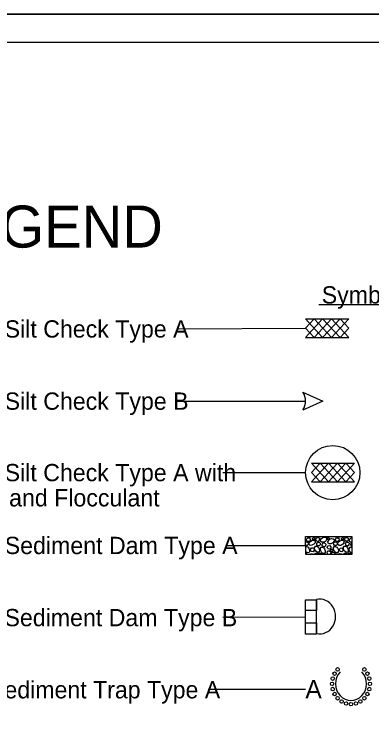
# Model space of a CAD drawing. Extents: x 1677124 to 1678808, y 1331209 to 1332299.
# Drawn here: x 1678246 to 1678527, y 1331745 to 1332299 of the extents above; entities that cross this region are included whole.
import ezdxf

# ---------------------------------------------------------------- set-up
doc = ezdxf.new("R2010")
doc.units = 0
for name, color, linetype in [('EC Title Sheet CELL', 7, 'Continuous'), ('Old_Level_1', 7, 'Continuous'), ('Sheet Plan CELL', 7, 'Continuous'), ('Sheet Plot Border Outside CELL', 7, 'Continuous'), ('z - Construction', 7, 'Continuous')]:
    doc.layers.add(name, color=color, linetype=linetype)

msp = doc.modelspace()

# ---------------------------------------------------------------- linework, layer by layer
at = {"layer": 'EC Title Sheet CELL'}
for p, q in [((1678485.11, 1332070.62), (1678547.36, 1332070.65)), ((1678481.61, 1332059.43), (1678474.81, 1332052.07)), ((1678474.83, 1332059.43), (1678508.58, 1332059.45)), ((1678488.15, 1332044.75), (1678474.83, 1332059.43)), ((1678488.17, 1332059.45), (1678474.85, 1332044.75)), ((1678495.22, 1332044.77), (1678481.61, 1332059.43)), ((1678495.22, 1332059.43), (1678481.63, 1332044.75)), ((1678501.78, 1332059.45), (1678488.15, 1332044.75)), ((1678501.78, 1332044.75), (1678488.17, 1332059.45)), ((1678508.58, 1332059.45), (1678495.22, 1332044.77)), ((1678508.58, 1332044.75), (1678495.22, 1332059.43)), ((1678508.58, 1332052.09), (1678501.78, 1332059.45)), ((1678375.11, 1332051.54), (1678474.81, 1332052.07)), ((1678481.63, 1332044.75), (1678474.81, 1332052.07)), ((1678508.58, 1332052.09), (1678501.78, 1332044.75)), ((1678474.85, 1332044.75), (1678508.58, 1332044.75)), ((1678472.7, 1332001.89), (1678488.4, 1331994.82)), ((1678374.14, 1331994.92), (1678474.81, 1331995)), ((1678488.4, 1331994.82), (1678472.7, 1331987.78)), ((1678486.23, 1331946.17), (1678479.43, 1331938.82)), ((1678492.77, 1331931.5), (1678479.45, 1331946.17)), ((1678479.45, 1331946.17), (1678513.18, 1331946.17)), ((1678492.79, 1331946.19), (1678479.47, 1331931.5)), ((1678499.84, 1331931.52), (1678486.23, 1331946.17)), ((1678499.84, 1331946.17), (1678486.25, 1331931.5)), ((1678506.4, 1331946.19), (1678492.77, 1331931.5)), ((1678506.4, 1331931.5), (1678492.79, 1331946.19)), ((1678513.2, 1331946.19), (1678499.84, 1331931.52)), ((1678513.2, 1331931.5), (1678499.84, 1331946.17)), ((1678513.2, 1331938.84), (1678506.4, 1331946.19)), ((1678410.01, 1331938.84), (1678474.81, 1331938.84)), ((1678486.25, 1331931.5), (1678479.43, 1331938.82)), ((1678513.2, 1331938.84), (1678506.4, 1331931.5)), ((1678479.47, 1331931.5), (1678513.2, 1331931.5)), ((1678412.2, 1331881.69), (1678474.81, 1331881.76)), ((1678474.67, 1331812.19), (1678474.69, 1331839.01)), ((1678474.67, 1331812.19), (1678474.69, 1331839.01)), ((1678483.31, 1331812.19), (1678483.32, 1331839.01)), ((1678483.31, 1331812.19), (1678483.32, 1331839.01)), ((1678409.88, 1331825.52), (1678474.68, 1331825.6)), ((1678483.31, 1331812.19), (1678474.67, 1331812.19)), ((1678483.31, 1331812.19), (1678474.67, 1331812.19)), ((1678398.44, 1331768.88), (1678474.68, 1331768.98))]:
    msp.add_line(p, q, dxfattribs=at)
for points in [[(1678474.69, 1331888.83), (1678511.07, 1331888.83), (1678511.09, 1331874.69), (1678474.93, 1331874.69)], [(1678474.69, 1331888.83), (1678511.07, 1331888.83), (1678511.09, 1331874.69), (1678474.93, 1331874.69)], [(1678474.69, 1331839.01), (1678483.32, 1331839.01), (1678483.31, 1331830.53), (1678474.69, 1331830.55)], [(1678474.67, 1331820.95), (1678483.32, 1331820.95), (1678483.31, 1331812.19), (1678474.67, 1331812.19)]]:
    msp.add_lwpolyline(points, close=True, dxfattribs=at)
for points in [[(1678474.95, 1331884.59), (1678474.95, 1331884.59), (1678475.99, 1331884.59), (1678477.05, 1331883.76), (1678476.77, 1331882.31), (1678475.99, 1331881.76), (1678474.95, 1331881.76), (1678474.95, 1331881.76)], [(1678474.95, 1331884.59), (1678474.95, 1331884.59), (1678475.99, 1331884.59), (1678477.05, 1331883.76), (1678476.77, 1331882.31), (1678475.99, 1331881.76), (1678474.95, 1331881.76), (1678474.95, 1331881.76)], [(1678475.46, 1331886.57), (1678476.5, 1331887.69), (1678477.54, 1331887.69), (1678478.37, 1331886.84), (1678478.34, 1331885.43), (1678477.56, 1331884.88), (1678476.24, 1331884.88), (1678475.75, 1331885.43), (1678475.46, 1331886.57)], [(1678475.46, 1331886.57), (1678476.5, 1331887.69), (1678477.54, 1331887.69), (1678478.37, 1331886.84), (1678478.34, 1331885.43), (1678477.56, 1331884.88), (1678476.24, 1331884.88), (1678475.75, 1331885.43), (1678475.46, 1331886.57)], [(1678479.13, 1331888.81), (1678478.87, 1331888.24), (1678477.56, 1331888.26), (1678477.31, 1331888.81)], [(1678479.13, 1331888.81), (1678478.87, 1331888.24), (1678477.56, 1331888.26), (1678477.31, 1331888.81)], [(1678478.87, 1331885.16), (1678480.17, 1331885.73), (1678481.49, 1331885.71), (1678482.27, 1331884.86), (1678482.27, 1331883.74), (1678481.21, 1331882.6), (1678479.66, 1331881.78), (1678478.34, 1331881.76), (1678477.54, 1331882.31), (1678477.56, 1331883.47), (1678478.07, 1331884.57), (1678478.87, 1331885.16)], [(1678478.87, 1331885.16), (1678480.17, 1331885.73), (1678481.49, 1331885.71), (1678482.27, 1331884.86), (1678482.27, 1331883.74), (1678481.21, 1331882.6), (1678479.66, 1331881.78), (1678478.34, 1331881.76), (1678477.54, 1331882.31), (1678477.56, 1331883.47), (1678478.07, 1331884.57), (1678478.87, 1331885.16)], [(1678480.17, 1331887.14), (1678480.7, 1331887.69), (1678481.47, 1331887.69), (1678482.02, 1331887.12), (1678482, 1331886.27), (1678481.24, 1331885.98), (1678480.68, 1331886), (1678480.17, 1331886.28), (1678480.17, 1331887.14)], [(1678480.17, 1331887.14), (1678480.7, 1331887.69), (1678481.47, 1331887.69), (1678482.02, 1331887.12), (1678482, 1331886.27), (1678481.24, 1331885.98), (1678480.68, 1331886), (1678480.17, 1331886.28), (1678480.17, 1331887.14)], [(1678483.06, 1331888.83), (1678482.8, 1331888.24), (1678481.49, 1331888.26), (1678481.23, 1331888.81)], [(1678483.06, 1331888.83), (1678482.8, 1331888.24), (1678481.49, 1331888.26), (1678481.23, 1331888.81)], [(1678482.78, 1331886.55), (1678483.59, 1331887.69), (1678484.88, 1331887.98), (1678485.69, 1331887.12), (1678485.4, 1331885.71), (1678484.63, 1331884.86), (1678483.57, 1331885.16), (1678482.8, 1331885.71), (1678482.78, 1331886.55)], [(1678482.78, 1331886.55), (1678483.59, 1331887.69), (1678484.88, 1331887.98), (1678485.69, 1331887.12), (1678485.4, 1331885.71), (1678484.63, 1331884.86), (1678483.57, 1331885.16), (1678482.8, 1331885.71), (1678482.78, 1331886.55)], [(1678483.61, 1331883.17), (1678484.36, 1331884.29), (1678485.4, 1331884.29), (1678486.2, 1331883.47), (1678486.2, 1331882.05), (1678485.42, 1331881.5), (1678484.36, 1331881.48), (1678483.57, 1331882.03), (1678483.61, 1331883.17)], [(1678483.61, 1331883.17), (1678484.36, 1331884.29), (1678485.4, 1331884.29), (1678486.2, 1331883.47), (1678486.2, 1331882.05), (1678485.42, 1331881.5), (1678484.36, 1331881.48), (1678483.57, 1331882.03), (1678483.61, 1331883.17)], [(1678488.05, 1331887.69), (1678489.34, 1331888.26), (1678490.64, 1331888.24), (1678491.17, 1331887.41), (1678491.17, 1331886.28), (1678490.38, 1331884.88), (1678488.82, 1331884.31), (1678487.52, 1331884.31), (1678486.73, 1331884.88), (1678486.46, 1331886), (1678487.24, 1331887.12), (1678488.05, 1331887.69)], [(1678488.05, 1331887.69), (1678489.34, 1331888.26), (1678490.64, 1331888.24), (1678491.17, 1331887.41), (1678491.17, 1331886.28), (1678490.38, 1331884.88), (1678488.82, 1331884.31), (1678487.52, 1331884.31), (1678486.73, 1331884.88), (1678486.46, 1331886), (1678487.24, 1331887.12), (1678488.05, 1331887.69)], [(1678490.13, 1331888.81), (1678490.13, 1331888.55), (1678488.81, 1331888.55), (1678488.81, 1331888.81)], [(1678490.13, 1331888.81), (1678490.13, 1331888.55), (1678488.81, 1331888.55), (1678488.81, 1331888.81)], [(1678491.68, 1331887.12), (1678492.23, 1331887.96), (1678492.75, 1331887.98), (1678493.27, 1331887.39), (1678493.28, 1331886.55), (1678492.74, 1331886.27), (1678491.94, 1331886.28), (1678491.7, 1331886.57), (1678491.68, 1331887.12)], [(1678491.68, 1331887.12), (1678492.23, 1331887.96), (1678492.75, 1331887.98), (1678493.27, 1331887.39), (1678493.28, 1331886.55), (1678492.74, 1331886.27), (1678491.94, 1331886.28), (1678491.7, 1331886.57), (1678491.68, 1331887.12)], [(1678493.51, 1331886.55), (1678495.1, 1331887.14), (1678496.4, 1331886.84), (1678497.2, 1331886.28), (1678497.2, 1331885.16), (1678496.14, 1331883.74), (1678494.59, 1331882.9), (1678493.25, 1331882.88), (1678492.47, 1331883.45), (1678492.23, 1331884.59), (1678493, 1331885.71), (1678493.78, 1331886.55)], [(1678493.51, 1331886.55), (1678495.1, 1331887.14), (1678496.4, 1331886.84), (1678497.2, 1331886.28), (1678497.2, 1331885.16), (1678496.14, 1331883.74), (1678494.59, 1331882.9), (1678493.25, 1331882.88), (1678492.47, 1331883.45), (1678492.23, 1331884.59), (1678493, 1331885.71), (1678493.78, 1331886.55)], [(1678496.65, 1331883.45), (1678497.73, 1331884.57), (1678498.77, 1331884.59), (1678499.54, 1331883.74), (1678499.54, 1331882.33), (1678498.75, 1331881.76), (1678497.48, 1331881.76), (1678496.93, 1331882.33), (1678496.65, 1331883.45)], [(1678496.65, 1331883.45), (1678497.73, 1331884.57), (1678498.77, 1331884.59), (1678499.54, 1331883.74), (1678499.54, 1331882.33), (1678498.75, 1331881.76), (1678497.48, 1331881.76), (1678496.93, 1331882.33), (1678496.65, 1331883.45)], [(1678498.24, 1331886.55), (1678499.01, 1331887.69), (1678500.05, 1331887.69), (1678501.13, 1331886.85), (1678500.85, 1331885.43), (1678500.09, 1331884.86), (1678499.03, 1331884.86), (1678498.48, 1331885.43), (1678498.24, 1331886.55)], [(1678498.24, 1331886.55), (1678499.01, 1331887.69), (1678500.05, 1331887.69), (1678501.13, 1331886.85), (1678500.85, 1331885.43), (1678500.09, 1331884.86), (1678499.03, 1331884.86), (1678498.48, 1331885.43), (1678498.24, 1331886.55)], [(1678501.9, 1331888.81), (1678501.37, 1331888.24), (1678500.07, 1331888.26), (1678499.81, 1331888.81)], [(1678501.9, 1331888.81), (1678501.37, 1331888.24), (1678500.07, 1331888.26), (1678499.81, 1331888.81)], [(1678501.39, 1331885.14), (1678502.98, 1331885.71), (1678504.26, 1331885.73), (1678504.78, 1331884.88), (1678504.78, 1331883.76), (1678503.98, 1331882.62), (1678502.41, 1331881.76), (1678501.13, 1331881.76), (1678500.07, 1331882.33), (1678500.07, 1331883.47), (1678500.6, 1331884.59), (1678501.39, 1331885.14)], [(1678501.39, 1331885.14), (1678502.98, 1331885.71), (1678504.26, 1331885.73), (1678504.78, 1331884.88), (1678504.78, 1331883.76), (1678503.98, 1331882.62), (1678502.41, 1331881.76), (1678501.13, 1331881.76), (1678500.07, 1331882.33), (1678500.07, 1331883.47), (1678500.6, 1331884.59), (1678501.39, 1331885.14)], [(1678502.96, 1331887.12), (1678503.21, 1331887.69), (1678504.02, 1331887.67), (1678504.53, 1331887.12), (1678504.51, 1331886.27), (1678504, 1331886), (1678503.22, 1331886), (1678502.96, 1331886.28), (1678502.96, 1331887.12)], [(1678502.96, 1331887.12), (1678503.21, 1331887.69), (1678504.02, 1331887.67), (1678504.53, 1331887.12), (1678504.51, 1331886.27), (1678504, 1331886), (1678503.22, 1331886), (1678502.96, 1331886.28), (1678502.96, 1331887.12)], [(1678505.82, 1331888.81), (1678505.57, 1331888.26), (1678504.26, 1331888.26), (1678504, 1331888.83)], [(1678505.82, 1331888.81), (1678505.57, 1331888.26), (1678504.26, 1331888.26), (1678504, 1331888.83)], [(1678505.29, 1331886.55), (1678506.08, 1331887.69), (1678507.4, 1331887.96), (1678508.18, 1331887.12), (1678508.18, 1331885.71), (1678507.4, 1331885.14), (1678506.12, 1331885.14), (1678505.57, 1331885.71), (1678505.29, 1331886.55)], [(1678505.29, 1331886.55), (1678506.08, 1331887.69), (1678507.4, 1331887.96), (1678508.18, 1331887.12), (1678508.18, 1331885.71), (1678507.4, 1331885.14), (1678506.12, 1331885.14), (1678505.57, 1331885.71), (1678505.29, 1331886.55)], [(1678506.1, 1331883.19), (1678506.87, 1331884.31), (1678508.18, 1331884.31), (1678508.97, 1331883.45), (1678508.71, 1331882.07), (1678508.18, 1331881.48), (1678506.86, 1331881.48), (1678506.34, 1331882.05), (1678506.1, 1331883.19)], [(1678506.1, 1331883.19), (1678506.87, 1331884.31), (1678508.18, 1331884.31), (1678508.97, 1331883.45), (1678508.71, 1331882.07), (1678508.18, 1331881.48), (1678506.86, 1331881.48), (1678506.34, 1331882.05), (1678506.1, 1331883.19)], [(1678511.05, 1331884.31), (1678510.01, 1331884.31), (1678509.24, 1331884.88), (1678509.22, 1331886), (1678509.75, 1331887.14), (1678510.52, 1331887.69)], [(1678511.05, 1331884.31), (1678510.01, 1331884.31), (1678509.24, 1331884.88), (1678509.22, 1331886), (1678509.75, 1331887.14), (1678510.52, 1331887.69)], [(1678510.52, 1331887.69), (1678511.07, 1331887.71)], [(1678510.52, 1331887.69), (1678511.07, 1331887.71)], [(1678474.69, 1331880.92), (1678475.73, 1331880.92), (1678476.77, 1331880.37), (1678477.3, 1331879.52)], [(1678474.69, 1331880.92), (1678475.73, 1331880.92), (1678476.77, 1331880.37), (1678477.3, 1331879.52)], [(1678477.3, 1331879.52), (1678477.81, 1331878.07), (1678477.83, 1331876.69), (1678477.3, 1331876.14), (1678475.99, 1331875.83), (1678474.69, 1331876.99)], [(1678477.3, 1331879.52), (1678477.81, 1331878.07), (1678477.83, 1331876.69), (1678477.3, 1331876.14), (1678475.99, 1331875.83), (1678474.69, 1331876.99)], [(1678478.6, 1331878.38), (1678479.38, 1331879.78), (1678480.7, 1331879.78), (1678481.47, 1331878.64), (1678481.24, 1331877.52), (1678480.72, 1331876.71), (1678479.38, 1331876.95), (1678478.87, 1331877.54), (1678478.6, 1331878.38)], [(1678478.6, 1331878.38), (1678479.38, 1331879.78), (1678480.7, 1331879.78), (1678481.47, 1331878.64), (1678481.24, 1331877.52), (1678480.72, 1331876.71), (1678479.38, 1331876.95), (1678478.87, 1331877.54), (1678478.6, 1331878.38)], [(1678485.16, 1331879.78), (1678485.67, 1331878.11), (1678485.4, 1331876.97), (1678484.89, 1331876.12), (1678483.85, 1331876.4), (1678482.8, 1331877.26), (1678481.74, 1331878.64), (1678482.02, 1331880.35), (1678482.53, 1331881.21), (1678483.57, 1331881.21), (1678484.36, 1331880.64), (1678485.16, 1331879.78)], [(1678485.16, 1331879.78), (1678485.67, 1331878.11), (1678485.4, 1331876.97), (1678484.89, 1331876.12), (1678483.85, 1331876.4), (1678482.8, 1331877.26), (1678481.74, 1331878.64), (1678482.02, 1331880.35), (1678482.53, 1331881.21), (1678483.57, 1331881.21), (1678484.36, 1331880.64), (1678485.16, 1331879.78)], [(1678489.6, 1331878.95), (1678490.11, 1331877.54), (1678490.13, 1331876.12), (1678489.6, 1331875.26), (1678488.31, 1331875.28), (1678487.24, 1331876.4), (1678486.44, 1331878.09), (1678486.46, 1331879.52), (1678486.97, 1331880.35), (1678488.01, 1331880.35), (1678489.07, 1331879.78), (1678489.6, 1331878.95)], [(1678489.6, 1331878.95), (1678490.11, 1331877.54), (1678490.13, 1331876.12), (1678489.6, 1331875.26), (1678488.31, 1331875.28), (1678487.24, 1331876.4), (1678486.44, 1331878.09), (1678486.46, 1331879.52), (1678486.97, 1331880.35), (1678488.01, 1331880.35), (1678489.07, 1331879.78), (1678489.6, 1331878.95)], [(1678487.77, 1331882.31), (1678488.3, 1331883.76), (1678489.62, 1331883.74), (1678490.66, 1331882.62), (1678490.39, 1331881.5), (1678489.6, 1331880.62), (1678488.54, 1331880.92), (1678487.78, 1331881.48), (1678487.77, 1331882.31)], [(1678487.77, 1331882.31), (1678488.3, 1331883.76), (1678489.62, 1331883.74), (1678490.66, 1331882.62), (1678490.39, 1331881.5), (1678489.6, 1331880.62), (1678488.54, 1331880.92), (1678487.78, 1331881.48), (1678487.77, 1331882.31)], [(1678491.68, 1331880.35), (1678492.47, 1331881.5), (1678493.79, 1331881.76), (1678494.57, 1331880.64), (1678494.57, 1331879.52), (1678493.78, 1331878.64), (1678492.47, 1331878.93), (1678491.96, 1331879.5), (1678491.68, 1331880.35)], [(1678491.68, 1331880.35), (1678492.47, 1331881.5), (1678493.79, 1331881.76), (1678494.57, 1331880.64), (1678494.57, 1331879.52), (1678493.78, 1331878.64), (1678492.47, 1331878.93), (1678491.96, 1331879.5), (1678491.68, 1331880.35)], [(1678494.32, 1331878.09), (1678494.85, 1331878.66), (1678495.63, 1331878.66), (1678496.14, 1331878.38), (1678496.14, 1331877.52), (1678495.61, 1331876.95), (1678494.83, 1331876.95), (1678494.59, 1331877.52), (1678494.32, 1331878.09)], [(1678494.32, 1331878.09), (1678494.85, 1331878.66), (1678495.63, 1331878.66), (1678496.14, 1331878.38), (1678496.14, 1331877.52), (1678495.61, 1331876.95), (1678494.83, 1331876.95), (1678494.59, 1331877.52), (1678494.32, 1331878.09)], [(1678500.07, 1331879.5), (1678500.58, 1331878.09), (1678500.33, 1331876.69), (1678499.81, 1331875.85), (1678498.77, 1331875.83), (1678497.46, 1331876.95), (1678496.67, 1331878.66), (1678496.67, 1331880.07), (1678497.2, 1331880.92), (1678498.24, 1331880.92), (1678499.29, 1331880.35), (1678499.81, 1331879.5)], [(1678500.07, 1331879.5), (1678500.58, 1331878.09), (1678500.33, 1331876.69), (1678499.81, 1331875.85), (1678498.77, 1331875.83), (1678497.46, 1331876.95), (1678496.67, 1331878.66), (1678496.67, 1331880.07), (1678497.2, 1331880.92), (1678498.24, 1331880.92), (1678499.29, 1331880.35), (1678499.81, 1331879.5)], [(1678501.37, 1331878.38), (1678501.89, 1331879.5), (1678503.22, 1331879.78), (1678504, 1331878.66), (1678504, 1331877.54), (1678503.21, 1331876.67), (1678502.18, 1331876.95), (1678501.39, 1331877.52), (1678501.37, 1331878.38)], [(1678501.37, 1331878.38), (1678501.89, 1331879.5), (1678503.22, 1331879.78), (1678504, 1331878.66), (1678504, 1331877.54), (1678503.21, 1331876.67), (1678502.18, 1331876.95), (1678501.39, 1331877.52), (1678501.37, 1331878.38)], [(1678507.65, 1331879.78), (1678508.18, 1331878.4), (1678508.18, 1331876.95), (1678507.67, 1331876.12), (1678506.61, 1331876.42), (1678505.3, 1331877.24), (1678504.51, 1331878.66), (1678504.51, 1331880.35), (1678505.04, 1331881.19), (1678506.08, 1331881.19), (1678507.14, 1331880.62), (1678507.65, 1331879.78)], [(1678507.65, 1331879.78), (1678508.18, 1331878.4), (1678508.18, 1331876.95), (1678507.67, 1331876.12), (1678506.61, 1331876.42), (1678505.3, 1331877.24), (1678504.51, 1331878.66), (1678504.51, 1331880.35), (1678505.04, 1331881.19), (1678506.08, 1331881.19), (1678507.14, 1331880.62), (1678507.65, 1331879.78)], [(1678511.07, 1331875.26), (1678511.07, 1331875.26), (1678509.75, 1331876.38), (1678508.99, 1331878.09), (1678509.22, 1331879.5), (1678509.75, 1331880.35), (1678510.8, 1331880.35), (1678511.07, 1331880.09)], [(1678511.07, 1331875.26), (1678511.07, 1331875.26), (1678509.75, 1331876.38), (1678508.99, 1331878.09), (1678509.22, 1331879.5), (1678509.75, 1331880.35), (1678510.8, 1331880.35), (1678511.07, 1331880.09)], [(1678510.28, 1331882.62), (1678511.05, 1331883.74)], [(1678510.28, 1331882.62), (1678511.05, 1331883.74)], [(1678511.09, 1331880.91), (1678511.09, 1331880.91), (1678510.52, 1331881.48), (1678510.28, 1331882.62)], [(1678511.09, 1331880.91), (1678511.09, 1331880.91), (1678510.52, 1331881.48), (1678510.28, 1331882.62)], [(1678474.95, 1331875.83), (1678475.22, 1331875.55), (1678474.93, 1331874.69)], [(1678474.95, 1331875.83), (1678475.22, 1331875.55), (1678474.93, 1331874.69)], [(1678478.07, 1331874.71), (1678478.88, 1331874.99), (1678480.17, 1331874.99), (1678480.43, 1331874.71)], [(1678478.07, 1331874.71), (1678478.88, 1331874.99), (1678480.17, 1331874.99), (1678480.43, 1331874.71)], [(1678481.74, 1331874.71), (1678482.53, 1331875.55), (1678483.84, 1331875.83), (1678484.63, 1331874.99), (1678484.61, 1331874.71)], [(1678481.74, 1331874.71), (1678482.53, 1331875.55), (1678483.84, 1331875.83), (1678484.63, 1331874.99), (1678484.61, 1331874.71)], [(1678484.88, 1331874.71), (1678485.69, 1331875.55), (1678486.99, 1331875.83), (1678487.77, 1331874.71), (1678487.77, 1331874.71)], [(1678484.88, 1331874.71), (1678485.69, 1331875.55), (1678486.99, 1331875.83), (1678487.77, 1331874.71), (1678487.77, 1331874.71)], [(1678488.81, 1331874.71), (1678488.82, 1331874.98), (1678489.62, 1331874.99), (1678489.86, 1331874.71)], [(1678488.81, 1331874.71), (1678488.82, 1331874.98), (1678489.62, 1331874.99), (1678489.86, 1331874.71)], [(1678491.7, 1331876.4), (1678492.47, 1331877.52), (1678493.51, 1331877.52), (1678494.59, 1331876.69), (1678494.32, 1331875.28), (1678493.55, 1331874.69)], [(1678491.7, 1331876.4), (1678492.47, 1331877.52), (1678493.51, 1331877.52), (1678494.59, 1331876.69), (1678494.32, 1331875.28), (1678493.55, 1331874.69)], [(1678492.47, 1331874.71), (1678492.21, 1331874.71), (1678491.94, 1331875.26), (1678491.7, 1331876.4)], [(1678492.47, 1331874.71), (1678492.21, 1331874.71), (1678491.94, 1331875.26), (1678491.7, 1331876.4)], [(1678494.82, 1331874.69), (1678494.83, 1331875.01)], [(1678494.82, 1331874.69), (1678494.83, 1331875.01)], [(1678494.83, 1331875.01), (1678495.63, 1331876.4), (1678496.91, 1331876.4), (1678497.73, 1331875.57), (1678497.73, 1331874.71)], [(1678494.83, 1331875.01), (1678495.63, 1331876.4), (1678496.91, 1331876.4), (1678497.73, 1331875.57), (1678497.73, 1331874.71)], [(1678500.58, 1331874.69), (1678501.39, 1331875.28), (1678502.94, 1331874.99), (1678502.94, 1331874.73)], [(1678500.58, 1331874.69), (1678501.39, 1331875.28), (1678502.94, 1331874.99), (1678502.94, 1331874.73)], [(1678504.53, 1331874.71), (1678505.06, 1331875.57), (1678506.34, 1331875.83), (1678507.16, 1331874.99), (1678507.16, 1331874.71)], [(1678504.53, 1331874.71), (1678505.06, 1331875.57), (1678506.34, 1331875.83), (1678507.16, 1331874.99), (1678507.16, 1331874.71)], [(1678507.67, 1331874.71), (1678508.18, 1331875.55), (1678509.5, 1331875.83), (1678510.28, 1331874.71), (1678510.28, 1331874.71)], [(1678507.67, 1331874.71), (1678508.18, 1331875.55), (1678509.5, 1331875.83), (1678510.28, 1331874.71), (1678510.28, 1331874.71)]]:
    msp.add_lwpolyline(points, dxfattribs=at)
msp.add_circle((1678496.11, 1331938.84), 21.3, dxfattribs=at)
for centre, major_axis, start_param, end_param in [((1678463.85, 1331995), (0, -11.82), 0.944994, 2.196599), ((1678485.64, 1331825.9), (0, 13.68), 2.949905, 6.474869), ((1678485.64, 1331825.9), (0, 13.68), 2.949905, 6.474869), ((1678510.39, 1331773.12), (0, 13.13), 0.785389, 5.497624)]:
    msp.add_ellipse(centre, major_axis=major_axis, ratio=0.927398, start_param=start_param, end_param=end_param, dxfattribs=at)
for centre, major_axis in [((1678499.91, 1331784.43), (0, -1.41)), ((1678520.87, 1331784.42), (0, 1.41)), ((1678496.07, 1331777.26), (0, -1.41)), ((1678497.55, 1331781.11), (0, -1.41)), ((1678523.23, 1331781.11), (0, 1.41)), ((1678524.71, 1331777.26), (0, 1.41)), ((1678495.56, 1331773.12), (0, -1.41)), ((1678525.22, 1331773.12), (0, 1.41)), ((1678496.07, 1331768.98), (0, -1.41)), ((1678524.71, 1331768.98), (0, 1.41)), ((1678497.55, 1331765.13), (0, -1.41)), ((1678499.9, 1331761.81), (0, -1.41)), ((1678520.87, 1331761.81), (0, 1.41)), ((1678523.23, 1331765.12), (0, 1.41)), ((1678502.97, 1331759.27), (0, -1.41)), ((1678506.55, 1331757.68), (0, -1.41)), ((1678510.39, 1331757.13), (0, -1.41)), ((1678514.23, 1331757.68), (0, -1.41)), ((1678517.8, 1331759.27), (0, -1.41))]:
    msp.add_ellipse(centre, major_axis=major_axis, ratio=0.927398, dxfattribs=at)
at = {"layer": 'Sheet Plan CELL'}
msp.add_line((1678794.2, 1332276.27), (1677160.26, 1332276.27), dxfattribs=at)
at = {"layer": 'Sheet Plot Border Outside CELL'}
msp.add_lwpolyline([(1677124.14, 1332298.56), (1678807.57, 1332298.56), (1678807.57, 1331209.28), (1677124.14, 1331209.28)], close=True, dxfattribs=at)
at = {"layer": 'z - Construction'}
msp.add_line((1678807.57, 1332298.56), (1677124.14, 1332298.56), dxfattribs=at)

# ---------------------------------------------------------------- texts
at = {"layer": 'EC Title Sheet CELL'}
for s, height, p in [('Symbol', 13.565, (1678487.46, 1332071.48)), ('Temporary Rock Silt Check Type A', 13.5651, (1678099.78, 1332044.76)), ('Temporary Rock Silt Check Type B', 13.5651, (1678099.78, 1331988.14)), ('Temporary Rock Silt Check Type A with', 13.5651, (1678099.78, 1331932.05)), ('Excelsior Matting and Flocculant', 13.5651, (1678099.23, 1331912.3)), ('Temporary Rock Sediment Dam Type A', 13.5705, (1678099.78, 1331874.9)), ('Temporary Rock Sediment Dam Type B', 13.5651, (1678099.65, 1331818.29)), ('Rock Pipe Inlet Sediment Trap Type A', 13.5461, (1678099.78, 1331761.69)), ('A', 14.29, (1678474.68, 1331761.84))]:
    msp.add_text(s, height=height, dxfattribs=at).set_placement(p)
at = {"layer": 'Old_Level_1'}
msp.add_text('EROSION & SEDIMENT CONTROL LEGEND', height=32.964, rotation=360, dxfattribs=at).set_placement((1677456.68, 1332115.38))

doc.saveas('drawing.dxf')
